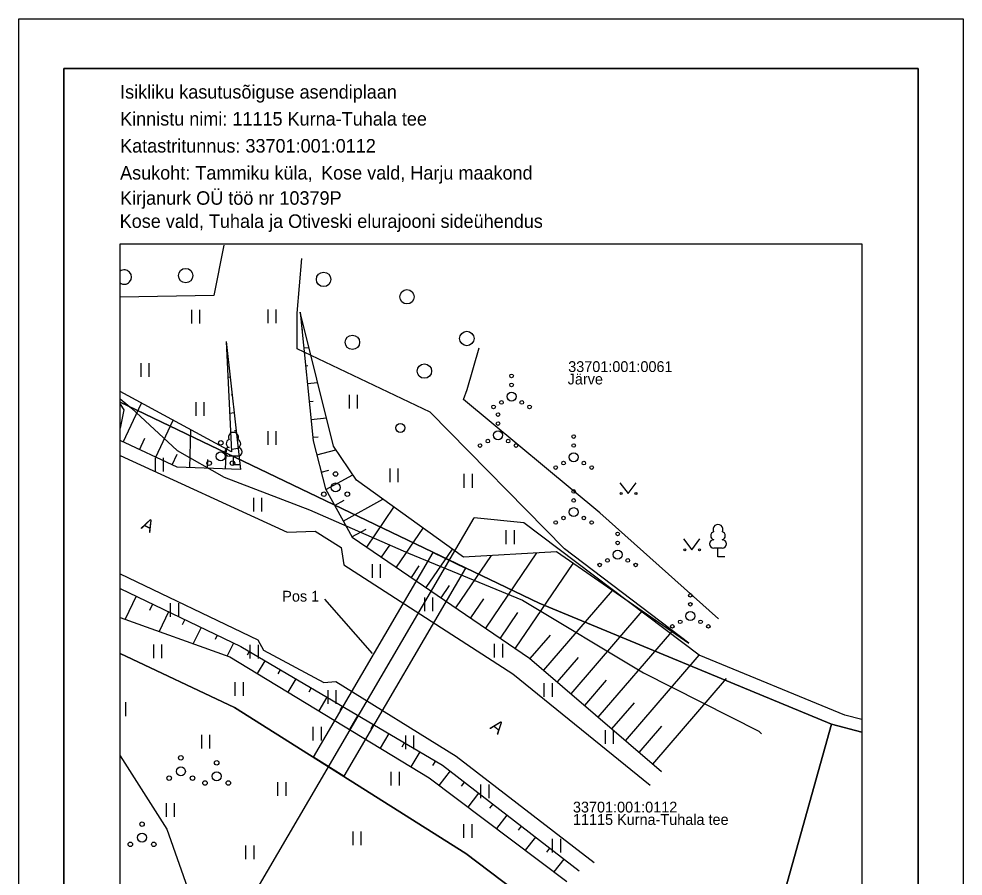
# Model space of a CAD drawing. Extents: x 555018.3 to 555070.8, y 6565612.3 to 6565686.5.
# Drawn here: x 555018.3 to 555070.8, y 6565638.8 to 6565686.5 of the extents above; entities that cross this region are included whole.
import ezdxf

# ---------------------------------------------------------------- set-up
doc = ezdxf.new("R2010")
doc.units = 0
for name, color, linetype in [('AED', 7, 'Continuous'), ('HALJASTUS', 7, 'Continuous'), ('KASUTUSALA', 7, 'Continuous'), ('KPKAABEL', 7, 'Continuous'), ('MPKAABEL', 7, 'Continuous'), ('PIIR', 7, 'Continuous'), ('POST', 7, 'Continuous'), ('PR_SIDE', 7, 'Continuous'), ('PUU', 7, 'Continuous'), ('RELJEEF', 7, 'Continuous'), ('TEE', 7, 'Continuous'), ('VORMISTUS', 7, 'Continuous')]:
    doc.layers.add(name, color=color, linetype=linetype)

msp = doc.modelspace()

# ---------------------------------------------------------------- linework, layer by layer
at = {"layer": 'AED'}
msp.add_lwpolyline([(555057.142, 6565653.162), (555050.543, 6565659.052), (555042.979, 6565665.343), (555043.174, 6565665.907), (555043.846, 6565668.219)], dxfattribs=at)
at = {"layer": 'HALJASTUS'}
for p, q in [((555027.847, 6565670.339), (555027.847, 6565669.578)), ((555028.302, 6565670.339), (555028.302, 6565669.578)), ((555032.085, 6565670.363), (555032.085, 6565669.602)), ((555032.54, 6565670.363), (555032.54, 6565669.602)), ((555025.03, 6565667.376), (555025.03, 6565666.614)), ((555025.485, 6565667.376), (555025.485, 6565666.614)), ((555036.611, 6565665.617), (555036.611, 6565664.856)), ((555037.066, 6565665.617), (555037.066, 6565664.856)), ((555028.088, 6565665.207), (555028.088, 6565664.446)), ((555028.543, 6565665.207), (555028.543, 6565664.446)), ((555032.085, 6565663.593), (555032.085, 6565662.832)), ((555032.54, 6565663.593), (555032.54, 6565662.832)), ((555025.825, 6565662.1), (555025.825, 6565661.338)), ((555026.28, 6565662.1), (555026.28, 6565661.338)), ((555038.874, 6565661.521), (555038.874, 6565660.76)), ((555039.329, 6565661.521), (555039.329, 6565660.76)), ((555042.991, 6565661.208), (555042.991, 6565660.447)), ((555043.446, 6565661.208), (555043.446, 6565660.447)), ((555051.669, 6565660.724), (555052.133, 6565660.117)), ((555052.133, 6565660.117), (555052.578, 6565660.724)), ((555031.29, 6565659.883), (555031.29, 6565659.122)), ((555031.745, 6565659.883), (555031.745, 6565659.122)), ((555045.327, 6565658.076), (555045.327, 6565657.315)), ((555045.782, 6565658.076), (555045.782, 6565657.315)), ((555055.209, 6565657.604), (555055.672, 6565656.997)), ((555055.672, 6565656.997), (555056.118, 6565657.604)), ((555037.887, 6565656.197), (555037.887, 6565655.436)), ((555038.342, 6565656.197), (555038.342, 6565655.436)), ((555040.8, 6565654.342), (555040.8, 6565653.581)), ((555041.255, 6565654.342), (555041.255, 6565653.581)), ((555026.671, 6565654.022), (555026.671, 6565653.261)), ((555027.126, 6565654.022), (555027.126, 6565653.261)), ((555025.733, 6565651.733), (555025.733, 6565650.972)), ((555026.188, 6565651.733), (555026.188, 6565650.972)), ((555031.098, 6565651.706), (555031.098, 6565650.945)), ((555031.553, 6565651.706), (555031.553, 6565650.945)), ((555044.676, 6565651.764), (555044.676, 6565651.003)), ((555045.132, 6565651.764), (555045.132, 6565651.003)), ((555030.263, 6565649.635), (555030.263, 6565648.874)), ((555030.718, 6565649.635), (555030.718, 6565648.874)), ((555047.445, 6565649.572), (555047.445, 6565648.811)), ((555047.9, 6565649.572), (555047.9, 6565648.811)), ((555035.423, 6565649.197), (555035.423, 6565648.436)), ((555035.878, 6565649.197), (555035.878, 6565648.436)), ((555024.187, 6565648.512), (555024.187, 6565647.751)), ((555034.597, 6565647.143), (555034.597, 6565646.381)), ((555035.052, 6565647.143), (555035.052, 6565646.381)), ((555050.84, 6565646.97), (555050.84, 6565646.209)), ((555051.295, 6565646.97), (555051.295, 6565646.209)), ((555028.397, 6565646.712), (555028.397, 6565645.951)), ((555028.852, 6565646.712), (555028.852, 6565645.951)), ((555039.741, 6565646.676), (555039.741, 6565645.915)), ((555040.196, 6565646.676), (555040.196, 6565645.915)), ((555038.932, 6565644.65), (555038.932, 6565643.889)), ((555039.387, 6565644.65), (555039.387, 6565643.889)), ((555032.631, 6565644.07), (555032.631, 6565643.309)), ((555033.086, 6565644.07), (555033.086, 6565643.309)), ((555043.92, 6565643.947), (555043.92, 6565643.186)), ((555044.375, 6565643.947), (555044.375, 6565643.186)), ((555026.438, 6565642.902), (555026.438, 6565642.141)), ((555026.893, 6565642.902), (555026.893, 6565642.141)), ((555042.975, 6565641.729), (555042.975, 6565640.968)), ((555043.43, 6565641.729), (555043.43, 6565640.968)), ((555036.817, 6565641.336), (555036.817, 6565640.575)), ((555037.272, 6565641.336), (555037.272, 6565640.575)), ((555030.852, 6565640.558), (555030.852, 6565639.797)), ((555031.307, 6565640.558), (555031.307, 6565639.797)), ((555047.907, 6565640.93), (555047.907, 6565640.169)), ((555048.362, 6565640.93), (555048.362, 6565640.169))]:
    msp.add_line(p, q, dxfattribs=at)
for points in [[(555029.652, 6565673.931), (555029.091, 6565671.127), (555023.875, 6565671.05)], [(555055.505, 6565651.803), (555048.596, 6565657.055), (555041.121, 6565664.646), (555033.726, 6565668.167), (555033.718, 6565670.144), (555033.986, 6565673.185)]]:
    msp.add_lwpolyline(points, dxfattribs=at)
for centre, radius in [((555027.525, 6565672.241), 0.4), ((555035.193, 6565672.03), 0.4), ((555039.828, 6565671.061), 0.4), ((555036.795, 6565668.531), 0.4), ((555043.157, 6565668.742), 0.4), ((555040.797, 6565666.929), 0.4), ((555045.644, 6565666.663), 0.1), ((555045.644, 6565665.513), 0.25), ((555045.644, 6565666.163), 0.1), ((555045.079, 6565665.188), 0.1), ((555046.209, 6565665.188), 0.1), ((555044.644, 6565664.938), 0.1), ((555046.644, 6565664.938), 0.1), ((555044.89, 6565664.513), 0.1), ((555044.89, 6565664.013), 0.1), ((555044.325, 6565663.038), 0.1), ((555044.89, 6565663.363), 0.25), ((555045.455, 6565663.038), 0.1), ((555049.099, 6565663.291), 0.1), ((555043.89, 6565662.788), 0.1), ((555045.89, 6565662.788), 0.1), ((555049.099, 6565662.791), 0.1), ((555049.099, 6565662.141), 0.25), ((555048.099, 6565661.566), 0.1), ((555048.534, 6565661.816), 0.1), ((555049.664, 6565661.816), 0.1), ((555050.099, 6565661.566), 0.1), ((555049.097, 6565660.237), 0.1), ((555051.732, 6565660.117), 0.055), ((555052.561, 6565660.117), 0.055), ((555049.097, 6565659.737), 0.1), ((555049.097, 6565659.087), 0.25), ((555048.097, 6565658.512), 0.1), ((555048.532, 6565658.762), 0.1), ((555049.662, 6565658.762), 0.1), ((555050.097, 6565658.512), 0.1), ((555051.541, 6565657.876), 0.1), ((555051.541, 6565657.376), 0.1), ((555051.541, 6565656.726), 0.25), ((555055.271, 6565656.997), 0.055), ((555056.1, 6565656.997), 0.055), ((555050.976, 6565656.401), 0.1), ((555052.106, 6565656.401), 0.1), ((555050.541, 6565656.151), 0.1), ((555052.541, 6565656.151), 0.1), ((555055.586, 6565654.461), 0.1), ((555055.586, 6565653.961), 0.1), ((555055.586, 6565653.311), 0.25), ((555054.586, 6565652.736), 0.1), ((555055.021, 6565652.986), 0.1), ((555056.151, 6565652.986), 0.1), ((555056.586, 6565652.736), 0.1)]:
    msp.add_circle(centre, radius, dxfattribs=at)
msp.add_arc((555024.112, 6565672.157), 0.4, 233.6848, 126.3152, dxfattribs=at)
at = {"layer": 'KASUTUSALA'}
msp.add_lwpolyline([(555041.279, 6565656.849), (555043.087, 6565655.98), (555036.315, 6565644.397), (555034.623, 6565645.465)], close=True, dxfattribs=at)
at = {"layer": 'KPKAABEL'}
for points in [[(555023.875, 6565665.09), (555024.08, 6565664.769), (555023.875, 6565663.759)], [(555023.875, 6565645.533), (555026.485, 6565641.465), (555030.606, 6565629.728), (555034.197, 6565621.515)]]:
    msp.add_lwpolyline(points, dxfattribs=at)
at = {"layer": 'MPKAABEL'}
msp.add_lwpolyline([(555023.875, 6565665.388), (555024.517, 6565664.875), (555027.056, 6565662.52), (555029.673, 6565661.024), (555034.413, 6565659.21), (555039.915, 6565656.802), (555046.244, 6565654.185), (555052.975, 6565650.153), (555059.391, 6565646.912), (555059.541, 6565646.762)], dxfattribs=at)
at = {"layer": 'PIIR'}
for points in [[(555065.125, 6565646.847), (555063.43, 6565647.29), (555047.17, 6565654.02), (555023.875, 6565665.204)], [(555023.875, 6565665.204), (555047.17, 6565654.02), (555063.43, 6565647.29), (555056.61, 6565622.91), (555053.62, 6565632.14), (555043.11, 6565640.11), (555030.24, 6565648.23), (555023.875, 6565651.228)], [(555023.875, 6565651.228), (555030.24, 6565648.23), (555043.11, 6565640.11), (555053.62, 6565632.14), (555056.61, 6565622.91), (555056.648, 6565621.515)], [(555056.648, 6565621.515), (555056.61, 6565622.91), (555063.43, 6565647.29), (555065.125, 6565646.847)]]:
    msp.add_lwpolyline(points, dxfattribs=at)
at = {"layer": 'POST'}
msp.add_circle((555039.46, 6565663.773), 0.25, dxfattribs=at)
at = {"layer": 'PR_SIDE'}
for points in [[(555033.062, 6565627.856), (555032.194, 6565629.84), (555030.448, 6565634.707), (555030.925, 6565637.158), (555043.563, 6565658.774)], [(555065.125, 6565647.548), (555064.179, 6565647.804), (555056.079, 6565651.133), (555046.326, 6565658.494), (555043.563, 6565658.774)]]:
    msp.add_lwpolyline(points, dxfattribs=at)
at = {"layer": 'PUU'}
for p, q in [((555030.422, 6565662.201), (555029.942, 6565662.201)), ((555030.182, 6565661.726), (555030.182, 6565662.201)), ((555030.562, 6565661.726), (555030.182, 6565661.726)), ((555057.361, 6565657.08), (555056.881, 6565657.08)), ((555057.121, 6565656.605), (555057.121, 6565657.08)), ((555057.501, 6565656.605), (555057.121, 6565656.605))]:
    msp.add_line(p, q, dxfattribs=at)
for centre, radius in [((555029.476, 6565662.937), 0.125), ((555029.476, 6565662.187), 0.25), ((555028.826, 6565661.812), 0.125), ((555030.126, 6565661.812), 0.125), ((555035.859, 6565661.208), 0.125), ((555035.859, 6565660.458), 0.25), ((555035.209, 6565660.083), 0.125), ((555036.509, 6565660.083), 0.125), ((555027.256, 6565645.424), 0.125), ((555029.249, 6565645.151), 0.125), ((555027.256, 6565644.674), 0.25), ((555026.606, 6565644.299), 0.125), ((555027.906, 6565644.299), 0.125), ((555029.249, 6565644.401), 0.25), ((555028.599, 6565644.026), 0.125), ((555029.899, 6565644.026), 0.125), ((555025.1, 6565641.741), 0.125), ((555025.1, 6565640.991), 0.25), ((555024.45, 6565640.616), 0.125), ((555025.75, 6565640.616), 0.125)]:
    msp.add_circle(centre, radius, dxfattribs=at)
for centre, radius, start, end in [((555030.182, 6565663.246), 0.277, 332.5799, 207.4201), ((555029.944, 6565662.439), 0.238, 90.0016, 269.3953), ((555030.012, 6565662.899), 0.233, 109.0217, 253.1415), ((555030.352, 6565662.899), 0.233, 286.8508, 70.9859), ((555030.419, 6565662.439), 0.238, 270.6047, 89.9984), ((555057.121, 6565658.125), 0.277, 332.5799, 207.4201), ((555056.951, 6565657.777), 0.233, 109.0217, 253.1415), ((555057.292, 6565657.777), 0.233, 286.8508, 70.9859), ((555056.884, 6565657.317), 0.238, 90.0016, 269.3953), ((555057.359, 6565657.317), 0.238, 270.6047, 89.9984)]:
    msp.add_arc(centre, radius, start, end, dxfattribs=at)
at = {"layer": 'RELJEEF'}
for p, q in [((555033.994, 6565669.217), (555034.036, 6565669.222)), ((555034.094, 6565668.222), (555034.378, 6565668.251)), ((555029.894, 6565667.589), (555029.875, 6565667.587)), ((555034.194, 6565667.227), (555034.322, 6565667.24)), ((555030.005, 6565666.595), (555029.88, 6565666.581)), ((555034.294, 6565666.232), (555034.863, 6565666.29)), ((555030.116, 6565665.601), (555030.06, 6565665.595)), ((555034.395, 6565665.237), (555034.608, 6565665.259)), ((555024.057, 6565662.981), (555025.068, 6565665.147)), ((555025.869, 6565662.135), (555026.831, 6565664.195)), ((555030.227, 6565664.607), (555029.978, 6565664.579)), ((555034.495, 6565664.242), (555035.348, 6565664.328)), ((555027.747, 6565661.559), (555027.82, 6565663.662)), ((555024.963, 6565662.558), (555025.259, 6565663.192)), ((555030.338, 6565663.613), (555030.244, 6565663.603)), ((555034.595, 6565663.247), (555034.893, 6565663.277)), ((555029.745, 6565661.489), (555029.785, 6565662.602)), ((555030.448, 6565662.62), (555030.075, 6565662.578)), ((555026.776, 6565661.712), (555027.057, 6565662.314)), ((555034.815, 6565662.274), (555035.879, 6565662.546)), ((555028.746, 6565661.524), (555028.763, 6565662.006)), ((555035.063, 6565661.305), (555035.486, 6565661.413)), ((555035.321, 6565660.34), (555036.813, 6565661.164)), ((555035.804, 6565659.465), (555036.34, 6565659.761)), ((555036.288, 6565658.589), (555038.489, 6565659.805)), ((555037.592, 6565657.146), (555039.103, 6565659.364)), ((555036.771, 6565657.714), (555037.556, 6565658.148)), ((555039.245, 6565656.02), (555040.728, 6565658.196)), ((555038.419, 6565656.583), (555038.868, 6565657.242)), ((555040.898, 6565654.894), (555042.352, 6565657.028)), ((555042.551, 6565653.768), (555044.529, 6565656.67)), ((555044.204, 6565652.642), (555047.053, 6565656.823)), ((555040.072, 6565655.457), (555040.512, 6565656.103)), ((555045.856, 6565651.515), (555049.075, 6565656.24)), ((555041.724, 6565654.331), (555042.187, 6565655.01)), ((555047.438, 6565650.296), (555051.257, 6565654.729)), ((555024.774, 6565654.414), (555024.157, 6565653.134)), ((555043.377, 6565653.205), (555044.101, 6565654.267)), ((555025.675, 6565653.979), (555025.504, 6565653.624)), ((555026.576, 6565653.545), (555026.05, 6565652.454)), ((555045.03, 6565652.078), (555045.997, 6565653.498)), ((555048.953, 6565648.99), (555052.911, 6565653.584)), ((555027.477, 6565653.111), (555027.332, 6565652.812)), ((555028.377, 6565652.677), (555027.942, 6565651.775)), ((555029.278, 6565652.243), (555029.161, 6565652)), ((555046.68, 6565650.949), (555047.805, 6565652.254)), ((555050.468, 6565647.685), (555054.564, 6565652.439)), ((555030.179, 6565651.808), (555029.835, 6565651.095)), ((555031.059, 6565651.335), (555030.935, 6565651.125)), ((555051.983, 6565646.379), (555056.079, 6565651.133)), ((555031.921, 6565650.828), (555031.502, 6565650.115)), ((555048.195, 6565649.643), (555049.362, 6565650.997)), ((555032.783, 6565650.322), (555032.655, 6565650.104)), ((555033.646, 6565649.816), (555033.212, 6565649.076)), ((555049.71, 6565648.338), (555050.919, 6565649.74)), ((555053.498, 6565645.074), (555057.594, 6565649.828)), ((555034.508, 6565649.309), (555034.375, 6565649.084)), ((555035.37, 6565648.803), (555034.921, 6565648.037)), ((555051.225, 6565647.032), (555052.475, 6565648.482)), ((555036.233, 6565648.297), (555036.096, 6565648.063)), ((555037.095, 6565647.79), (555036.63, 6565646.998)), ((555037.957, 6565647.284), (555037.816, 6565647.042)), ((555052.741, 6565645.727), (555053.99, 6565647.177)), ((555038.82, 6565646.778), (555038.339, 6565645.959)), ((555039.682, 6565646.271), (555039.536, 6565646.022)), ((555040.544, 6565645.765), (555040.048, 6565644.92)), ((555041.407, 6565645.258), (555041.256, 6565645.001)), ((555042.23, 6565644.695), (555041.608, 6565643.893)), ((555043.02, 6565644.082), (555042.836, 6565643.845)), ((555043.81, 6565643.469), (555043.206, 6565642.69)), ((555044.6, 6565642.855), (555044.422, 6565642.625)), ((555045.39, 6565642.242), (555044.804, 6565641.487)), ((555046.18, 6565641.629), (555046.007, 6565641.406)), ((555046.97, 6565641.016), (555046.402, 6565640.284)), ((555047.76, 6565640.403), (555047.592, 6565640.187)), ((555048.55, 6565639.79), (555048, 6565639.082))]:
    msp.add_line(p, q, dxfattribs=at)
for points in [[(555055.507, 6565651.786), (555048.138, 6565656.889), (555042.979, 6565656.577), (555037.014, 6565660.866), (555035.735, 6565662.759), (555033.894, 6565670.212)], [(555033.894, 6565670.212), (555034.614, 6565663.057), (555035.301, 6565660.376), (555036.779, 6565657.701), (555046.65, 6565650.974), (555053.976, 6565644.662)], [(555029.783, 6565668.583), (555030.578, 6565661.46), (555027.05, 6565661.583), (555023.875, 6565663.065)], [(555029.783, 6565668.583), (555030.081, 6565662.441), (555023.875, 6565665.791)], [(555023.875, 6565654.847), (555030.588, 6565651.611), (555041.809, 6565645.022), (555049.395, 6565639.133)], [(555023.875, 6565653.236), (555029.972, 6565651.046), (555041.058, 6565644.307), (555048.71, 6565638.547)]]:
    msp.add_lwpolyline(points, dxfattribs=at)
at = {"layer": 'TEE'}
for points in [[(555023.875, 6565662.238), (555033.164, 6565657.977), (555034.731, 6565658.02), (555036.161, 6565657.119), (555036.314, 6565656.164), (555045.718, 6565650.093), (555053.358, 6565643.906)], [(555023.875, 6565655.663), (555031.536, 6565651.986), (555031.846, 6565651.41), (555035.205, 6565649.618), (555035.879, 6565649.677), (555042.559, 6565645.526), (555050.244, 6565639.614)]]:
    msp.add_lwpolyline(points, dxfattribs=at)
at = {"layer": 'VORMISTUS'}
msp.add_line((555037.915, 6565651.23), (555035.253, 6565654.247), dxfattribs=at)
for points in [[(555018.25, 6565686.515), (555070.75, 6565686.515), (555070.75, 6565612.265), (555018.25, 6565612.265)], [(555020.75, 6565615.015), (555068.25, 6565615.015), (555068.25, 6565683.765), (555020.75, 6565683.765)], [(555020.75, 6565683.765), (555068.25, 6565683.765), (555068.25, 6565615.015), (555020.75, 6565615.015)], [(555065.125, 6565621.515), (555023.875, 6565621.515), (555023.875, 6565674.015), (555065.125, 6565674.015)]]:
    msp.add_lwpolyline(points, close=True, dxfattribs=at)

# ---------------------------------------------------------------- texts
at = {"layer": 'PIIR'}
for s, p in [('33701:001:0061', (555048.793, 6565666.879)), ('Järve', (555048.763, 6565666.188)), ('33701:001:0112', (555049.056, 6565642.386)), ('11115 Kurna-Tuhala tee', (555049.056, 6565641.695))]:
    msp.add_text(s, height=0.6, dxfattribs=at).set_placement(p)
at = {"layer": 'TEE'}
for rotation, p in [(333.5713, (555024.999, 6565658.194)), (321.6468, (555044.402, 6565647.079))]:
    msp.add_text('A', height=0.7, rotation=rotation, dxfattribs=at).set_placement(p)
at = {"layer": 'VORMISTUS'}
for s, p in [('Isikliku kasutusõiguse asendiplaan', (555023.878, 6565682.082)), ('Katastritunnus: 33701:001:0112', (555023.878, 6565679.082)), ('Kirjanurk OÜ töö nr 10379P', (555023.874, 6565676.18)), ('Kose vald, Tuhala ja Otiveski elurajooni sideühendus', (555023.855, 6565674.893))]:
    msp.add_text(s, height=0.75, rotation=360, dxfattribs=at).set_placement(p)
for s, height, p in [('Kinnistu nimi: 11115 Kurna-Tuhala tee', 0.75, (555023.878, 6565680.582)), ('Asukoht: Tammiku küla, ', 0.75, (555023.878, 6565677.582)), ('Kose vald, Harju maakond', 0.75, (555035.052, 6565677.582)), ('Pos 1', 0.6, (555032.895, 6565654.112))]:
    msp.add_text(s, height=height, dxfattribs=at).set_placement(p)

doc.saveas('drawing.dxf')
